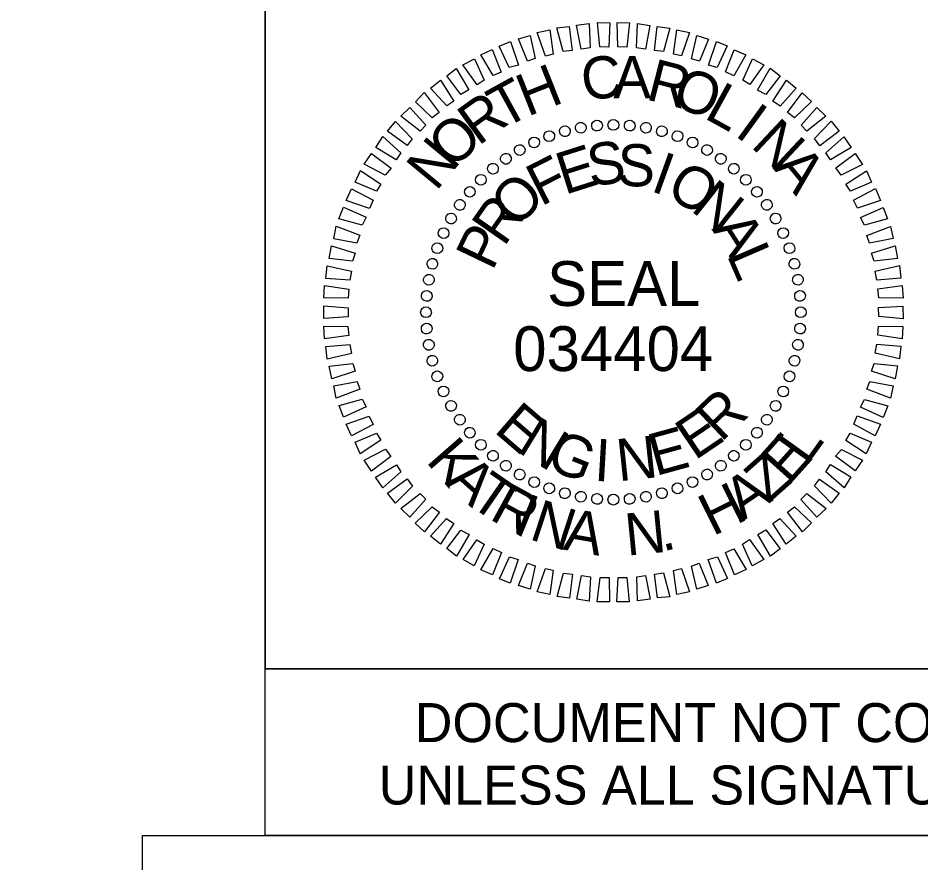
# Model space of a CAD drawing. Extents: x 2320980 to 2456309, y 595047 to 606177.
# Drawn here: x 2455995.13 to 2456020.58, y 596701.59 to 596725.41 of the extents above; entities that cross this region are included whole.
import ezdxf

# ---------------------------------------------------------------- set-up
doc = ezdxf.new("R2010")
doc.units = 0
for name, color, linetype in [('Prop Dimension', 7, 'Continuous'), ('Sheet Data Field CELL', 7, 'Continuous'), ('Sheet Plan CELL', 7, 'Continuous'), ('Sheet Sticker Exception Certification CELL', 7, 'Continuous')]:
    doc.layers.add(name, color=color, linetype=linetype)

msp = doc.modelspace()

# ---------------------------------------------------------------- linework, layer by layer
at = {"layer": 'Prop Dimension'}
msp.add_lwpolyline([(2455998.637, 596702.366), (2456042.107, 596702.366), (2456042.107, 596698.09), (2455998.637, 596698.09)], close=True, dxfattribs=at)
at = {"layer": 'Sheet Data Field CELL'}
for p, q in [((2456010.539, 596722.224), (2456010.539, 596722.224)), ((2456011.001, 596722.316), (2456011.001, 596722.316)), ((2456011.453, 596722.387), (2456011.453, 596722.387)), ((2456011.916, 596722.406), (2456011.916, 596722.406)), ((2456012.38, 596722.383), (2456012.38, 596722.383)), ((2456012.834, 596722.317), (2456012.834, 596722.317)), ((2456013.278, 596722.23), (2456013.278, 596722.23)), ((2456010.099, 596722.09), (2456010.099, 596722.09)), ((2456013.722, 596722.09), (2456013.722, 596722.09)), ((2456009.274, 596721.696), (2456009.274, 596721.696)), ((2456009.681, 596721.914), (2456009.681, 596721.914)), ((2456014.147, 596721.908), (2456014.147, 596721.908)), ((2456014.561, 596721.704), (2456014.561, 596721.704)), ((2456008.878, 596721.447), (2456008.878, 596721.447)), ((2456014.945, 596721.448), (2456014.945, 596721.448)), ((2456008.514, 596721.177), (2456008.514, 596721.177)), ((2456015.319, 596721.17), (2456015.319, 596721.17)), ((2456008.172, 596720.855), (2456008.172, 596720.855)), ((2456015.65, 596720.86), (2456015.65, 596720.86)), ((2456007.862, 596720.523), (2456007.862, 596720.523)), ((2456015.972, 596720.518), (2456015.972, 596720.518)), ((2456007.584, 596720.15), (2456007.584, 596720.15)), ((2456016.242, 596720.154), (2456016.242, 596720.154)), ((2456007.327, 596719.766), (2456007.327, 596719.766)), ((2456016.491, 596719.758), (2456016.491, 596719.758)), ((2456007.124, 596719.352), (2456007.124, 596719.352)), ((2456016.709, 596719.351), (2456016.709, 596719.351)), ((2456006.941, 596718.927), (2456006.941, 596718.927)), ((2456016.885, 596718.932), (2456016.885, 596718.932)), ((2456006.802, 596718.483), (2456006.802, 596718.483)), ((2456017.019, 596718.492), (2456017.019, 596718.492)), ((2456006.715, 596718.039), (2456006.715, 596718.039)), ((2456017.111, 596718.031), (2456017.111, 596718.031)), ((2456006.649, 596717.585), (2456006.649, 596717.585)), ((2456017.183, 596717.579), (2456017.183, 596717.579)), ((2456006.625, 596717.121), (2456006.625, 596717.121)), ((2456017.201, 596717.116), (2456017.201, 596717.116)), ((2456006.644, 596716.658), (2456006.644, 596716.658)), ((2456017.178, 596716.652), (2456017.178, 596716.652)), ((2456006.715, 596716.206), (2456006.715, 596716.206)), ((2456017.112, 596716.198), (2456017.112, 596716.198)), ((2456006.807, 596715.744), (2456006.807, 596715.744)), ((2456017.025, 596715.754), (2456017.025, 596715.754)), ((2456006.942, 596715.304), (2456006.942, 596715.304)), ((2456016.885, 596715.309), (2456016.885, 596715.309)), ((2456007.117, 596714.886), (2456007.117, 596714.886)), ((2456016.703, 596714.884), (2456016.703, 596714.884)), ((2456007.335, 596714.479), (2456007.335, 596714.479)), ((2456016.499, 596714.47), (2456016.499, 596714.47)), ((2456007.584, 596714.083), (2456007.584, 596714.083)), ((2456016.243, 596714.086), (2456016.243, 596714.086)), ((2456007.854, 596713.719), (2456007.854, 596713.719)), ((2456015.965, 596713.713), (2456015.965, 596713.713)), ((2456008.176, 596713.377), (2456008.176, 596713.377)), ((2456015.655, 596713.381), (2456015.655, 596713.381)), ((2456008.508, 596713.067), (2456008.508, 596713.067)), ((2456015.313, 596713.059), (2456015.313, 596713.059)), ((2456008.881, 596712.789), (2456008.881, 596712.789)), ((2456014.949, 596712.789), (2456014.949, 596712.789)), ((2456009.265, 596712.532), (2456009.265, 596712.532)), ((2456014.553, 596712.54), (2456014.553, 596712.54)), ((2456009.679, 596712.329), (2456009.679, 596712.329)), ((2456014.146, 596712.322), (2456014.146, 596712.322)), ((2456010.104, 596712.146), (2456010.104, 596712.146)), ((2456010.549, 596712.007), (2456010.549, 596712.007)), ((2456013.287, 596712.012), (2456013.287, 596712.012)), ((2456013.728, 596712.146), (2456013.728, 596712.146)), ((2456010.993, 596711.92), (2456010.993, 596711.92)), ((2456011.447, 596711.854), (2456011.447, 596711.854)), ((2456011.911, 596711.83), (2456011.911, 596711.83)), ((2456012.374, 596711.849), (2456012.374, 596711.849)), ((2456012.826, 596711.92), (2456012.826, 596711.92))]:
    msp.add_line(p, q, dxfattribs=at)
for points in [[(2456011.004, 596724.539), (2456010.877, 596725.211), (2456011.234, 596725.259), (2456011.256, 596724.575)], [(2456011.53, 596724.601), (2456011.465, 596725.284), (2456011.813, 596725.28), (2456011.783, 596724.595)], [(2456012.035, 596724.599), (2456012.023, 596725.284), (2456012.371, 596725.279), (2456012.288, 596724.593)], [(2456012.563, 596724.577), (2456012.593, 596725.262), (2456012.941, 596725.205), (2456012.816, 596724.539)], [(2456009.996, 596724.342), (2456009.764, 596725.002), (2456010.12, 596725.082), (2456010.217, 596724.399)], [(2456010.5, 596724.467), (2456010.32, 596725.138), (2456010.667, 596725.176), (2456010.752, 596724.503)], [(2456013.07, 596724.501), (2456013.152, 596725.177), (2456013.501, 596725.13), (2456013.323, 596724.474)], [(2456013.609, 596724.395), (2456013.702, 596725.081), (2456014.061, 596725.003), (2456013.831, 596724.346)], [(2456008.98, 596724.019), (2456008.696, 596724.625), (2456009.01, 596724.757), (2456009.243, 596724.087)], [(2456009.493, 596724.197), (2456009.24, 596724.824), (2456009.565, 596724.924), (2456009.713, 596724.274)], [(2456014.116, 596724.267), (2456014.263, 596724.922), (2456014.591, 596724.823), (2456014.339, 596724.197)], [(2456014.593, 596724.085), (2456014.824, 596724.753), (2456015.121, 596724.632), (2456014.837, 596724.016)], [(2456008.521, 596723.79), (2456008.174, 596724.374), (2456008.497, 596724.527), (2456008.751, 596723.889)], [(2456015.071, 596723.894), (2456015.323, 596724.519), (2456015.652, 596724.378), (2456015.305, 596723.782)], [(2456008.073, 596723.529), (2456007.673, 596724.091), (2456007.996, 596724.265), (2456008.27, 596723.659)], [(2456015.559, 596723.66), (2456015.833, 596724.265), (2456016.152, 596724.092), (2456015.762, 596723.537)], [(2456007.614, 596723.258), (2456007.215, 596723.788), (2456007.485, 596723.993), (2456007.843, 596723.388)], [(2456015.975, 596723.383), (2456016.333, 596724), (2456016.611, 596723.784), (2456016.209, 596723.26)], [(2456007.219, 596722.935), (2456006.757, 596723.433), (2456007.038, 596723.659), (2456007.417, 596723.075)], [(2456016.412, 596723.074), (2456016.792, 596723.66), (2456017.07, 596723.433), (2456016.615, 596722.93)], [(2456006.804, 596722.601), (2456006.332, 596723.056), (2456006.581, 596723.314), (2456007.001, 596722.752)], [(2456016.818, 596722.755), (2456017.24, 596723.31), (2456017.498, 596723.062), (2456017.021, 596722.6)], [(2456006.463, 596722.226), (2456005.918, 596722.649), (2456006.177, 596722.896), (2456006.628, 596722.398)], [(2456017.204, 596722.393), (2456017.648, 596722.896), (2456017.905, 596722.647), (2456017.365, 596722.227)], [(2456006.101, 596721.82), (2456005.546, 596722.221), (2456005.773, 596722.499), (2456006.245, 596722.012)], [(2456017.579, 596722.02), (2456018.055, 596722.503), (2456018.281, 596722.222), (2456017.73, 596721.812)], [(2456005.792, 596721.414), (2456005.217, 596721.762), (2456005.412, 596722.071), (2456005.926, 596721.617)], [(2456017.902, 596721.615), (2456018.41, 596722.066), (2456018.616, 596721.764), (2456018.032, 596721.417)], [(2456005.484, 596720.988), (2456004.888, 596721.293), (2456005.094, 596721.592), (2456005.649, 596721.18)], [(2456018.183, 596721.188), (2456018.734, 596721.598), (2456018.94, 596721.286), (2456018.334, 596720.98)], [(2456005.239, 596720.53), (2456004.634, 596720.783), (2456004.786, 596721.112), (2456005.362, 596720.733)], [(2456018.465, 596720.73), (2456019.048, 596721.108), (2456019.191, 596720.784), (2456018.595, 596720.532)], [(2456005.037, 596720.042), (2456004.379, 596720.273), (2456004.532, 596720.602), (2456005.138, 596720.276)], [(2456018.684, 596720.281), (2456019.299, 596720.607), (2456019.442, 596720.273), (2456018.793, 596720.051)], [(2456004.834, 596719.575), (2456004.178, 596719.753), (2456004.309, 596720.082), (2456004.946, 596719.798)], [(2456018.882, 596719.789), (2456019.519, 596720.074), (2456019.641, 596719.749), (2456018.991, 596719.57)], [(2456004.685, 596719.067), (2456004.03, 596719.193), (2456004.097, 596719.541), (2456004.765, 596719.29)], [(2456019.059, 596719.286), (2456019.729, 596719.54), (2456019.798, 596719.194), (2456019.137, 596719.067)], [(2456004.557, 596718.559), (2456003.902, 596718.632), (2456003.97, 596718.991), (2456004.637, 596718.782)], [(2456019.194, 596718.783), (2456019.854, 596718.995), (2456019.924, 596718.638), (2456019.261, 596718.563)], [(2456004.482, 596718.021), (2456003.807, 596718.072), (2456003.843, 596718.431), (2456004.53, 596718.274)], [(2456019.298, 596718.279), (2456019.98, 596718.439), (2456020.018, 596718.081), (2456019.345, 596718.027)], [(2456004.438, 596717.514), (2456003.753, 596717.523), (2456003.768, 596717.871), (2456004.455, 596717.767)], [(2456019.37, 596717.775), (2456020.053, 596717.871), (2456020.08, 596717.514), (2456019.395, 596717.523)], [(2456004.437, 596716.988), (2456003.753, 596716.944), (2456003.747, 596717.302), (2456004.432, 596717.24)], [(2456019.39, 596717.249), (2456020.074, 596717.292), (2456020.08, 596716.934), (2456019.394, 596716.996)], [(2456004.456, 596716.461), (2456003.774, 596716.365), (2456003.746, 596716.723), (2456004.431, 596716.714)], [(2456019.388, 596716.722), (2456020.073, 596716.713), (2456020.058, 596716.365), (2456019.372, 596716.469)], [(2456004.529, 596715.957), (2456003.847, 596715.798), (2456003.809, 596716.155), (2456004.482, 596716.209)], [(2456019.344, 596716.216), (2456020.02, 596716.164), (2456019.984, 596715.805), (2456019.296, 596715.962)], [(2456004.632, 596715.453), (2456003.972, 596715.242), (2456003.903, 596715.598), (2456004.565, 596715.673)], [(2456019.27, 596715.677), (2456019.924, 596715.604), (2456019.856, 596715.245), (2456019.189, 596715.454)], [(2456004.767, 596714.95), (2456004.098, 596714.696), (2456004.028, 596715.042), (2456004.69, 596715.17)], [(2456019.142, 596715.169), (2456019.797, 596715.044), (2456019.729, 596714.695), (2456019.061, 596714.947)], [(2456004.945, 596714.447), (2456004.307, 596714.162), (2456004.186, 596714.487), (2456004.835, 596714.667)], [(2456018.992, 596714.661), (2456019.649, 596714.483), (2456019.517, 596714.154), (2456018.88, 596714.438)], [(2456005.143, 596713.956), (2456004.527, 596713.629), (2456004.384, 596713.964), (2456005.033, 596714.186)], [(2456018.79, 596714.194), (2456019.447, 596713.963), (2456019.295, 596713.634), (2456018.689, 596713.961)], [(2456005.361, 596713.507), (2456004.778, 596713.128), (2456004.635, 596713.452), (2456005.231, 596713.705)], [(2456018.588, 596713.706), (2456019.193, 596713.453), (2456019.04, 596713.124), (2456018.465, 596713.504)], [(2456005.643, 596713.048), (2456005.092, 596712.638), (2456004.886, 596712.951), (2456005.492, 596713.256)], [(2456018.343, 596713.249), (2456018.938, 596712.943), (2456018.733, 596712.645), (2456018.178, 596713.056)], [(2456005.924, 596712.621), (2456005.416, 596712.17), (2456005.211, 596712.472), (2456005.795, 596712.819)], [(2456018.034, 596712.822), (2456018.609, 596712.474), (2456018.415, 596712.165), (2456017.901, 596712.62)], [(2456006.248, 596712.216), (2456005.771, 596711.734), (2456005.545, 596712.014), (2456006.096, 596712.424)], [(2456017.725, 596712.416), (2456018.28, 596712.015), (2456018.053, 596711.737), (2456017.581, 596712.224)], [(2456006.623, 596711.843), (2456006.179, 596711.341), (2456005.921, 596711.589), (2456006.462, 596712.009)], [(2456017.364, 596712.01), (2456017.909, 596711.587), (2456017.649, 596711.341), (2456017.198, 596711.838)], [(2456007.008, 596711.481), (2456006.586, 596710.926), (2456006.329, 596711.175), (2456006.805, 596711.636)], [(2456017.023, 596711.635), (2456017.494, 596711.18), (2456017.246, 596710.923), (2456016.825, 596711.484)], [(2456007.414, 596711.162), (2456007.035, 596710.576), (2456006.757, 596710.803), (2456007.212, 596711.306)], [(2456016.607, 596711.301), (2456017.069, 596710.804), (2456016.788, 596710.578), (2456016.41, 596711.161)], [(2456007.851, 596710.854), (2456007.493, 596710.236), (2456007.216, 596710.453), (2456007.617, 596710.976)], [(2456016.213, 596710.979), (2456016.612, 596710.448), (2456016.341, 596710.243), (2456015.983, 596710.848)], [(2456008.267, 596710.577), (2456007.993, 596709.971), (2456007.674, 596710.145), (2456008.065, 596710.699)], [(2456015.754, 596710.707), (2456016.154, 596710.145), (2456015.83, 596709.971), (2456015.556, 596710.577)], [(2456008.756, 596710.343), (2456008.503, 596709.717), (2456008.174, 596709.859), (2456008.522, 596710.455)], [(2456009.233, 596710.151), (2456009.002, 596709.483), (2456008.705, 596709.604), (2456008.989, 596710.22)], [(2456014.846, 596710.217), (2456015.131, 596709.611), (2456014.817, 596709.479), (2456014.584, 596710.149)], [(2456015.306, 596710.446), (2456015.653, 596709.863), (2456015.329, 596709.71), (2456015.076, 596710.348)], [(2456009.71, 596709.97), (2456009.564, 596709.314), (2456009.235, 596709.414), (2456009.488, 596710.039)], [(2456014.333, 596710.04), (2456014.586, 596709.412), (2456014.262, 596709.312), (2456014.113, 596709.962)], [(2456010.218, 596709.842), (2456010.125, 596709.155), (2456009.765, 596709.233), (2456009.996, 596709.89)], [(2456010.757, 596709.735), (2456010.674, 596709.06), (2456010.326, 596709.106), (2456010.504, 596709.762)], [(2456013.327, 596709.769), (2456013.507, 596709.098), (2456013.16, 596709.061), (2456013.074, 596709.733)], [(2456013.83, 596709.894), (2456014.063, 596709.235), (2456013.706, 596709.155), (2456013.61, 596709.838)], [(2456011.264, 596709.66), (2456011.234, 596708.975), (2456010.885, 596709.032), (2456011.01, 596709.697)], [(2456011.791, 596709.637), (2456011.803, 596708.953), (2456011.455, 596708.957), (2456011.538, 596709.643)], [(2456012.297, 596709.636), (2456012.361, 596708.952), (2456012.014, 596708.957), (2456012.044, 596709.642)], [(2456012.822, 596709.697), (2456012.95, 596709.026), (2456012.593, 596708.977), (2456012.57, 596709.661)]]:
    msp.add_lwpolyline(points, close=True, dxfattribs=at)
for centre, major_axis in [((2456010.996, 596722.321), (-0.026, 0.149)), ((2456011.453, 596722.381), (-0.013, 0.151)), ((2456011.913, 596722.401), (0, 0.152)), ((2456012.374, 596722.381), (0.013, 0.151)), ((2456012.831, 596722.321), (0.026, 0.149)), ((2456010.106, 596722.082), (-0.052, 0.143)), ((2456010.546, 596722.221), (-0.039, 0.146)), ((2456013.281, 596722.221), (0.039, 0.146)), ((2456013.72, 596722.082), (0.052, 0.143)), ((2456009.681, 596721.906), (-0.064, 0.137)), ((2456014.146, 596721.906), (0.064, 0.137)), ((2456009.272, 596721.693), (-0.076, 0.131)), ((2456014.555, 596721.693), (0.076, 0.131)), ((2456008.883, 596721.446), (-0.087, 0.124)), ((2456014.943, 596721.446), (0.087, 0.124)), ((2456008.518, 596721.165), (-0.097, 0.116)), ((2456015.309, 596721.165), (0.097, 0.116)), ((2456008.178, 596720.854), (-0.107, 0.107)), ((2456015.649, 596720.854), (0.107, 0.107)), ((2456007.866, 596720.514), (-0.116, 0.097)), ((2456015.96, 596720.514), (0.116, 0.097)), ((2456007.586, 596720.148), (-0.124, 0.087)), ((2456016.241, 596720.148), (0.124, 0.087)), ((2456007.338, 596719.76), (-0.131, 0.076)), ((2456016.488, 596719.76), (0.131, 0.076)), ((2456007.125, 596719.351), (-0.137, 0.064)), ((2456016.701, 596719.351), (0.137, 0.064)), ((2456006.949, 596718.925), (-0.143, 0.052)), ((2456016.877, 596718.925), (0.143, 0.052)), ((2456006.81, 596718.485), (-0.146, 0.039)), ((2456017.016, 596718.485), (0.146, 0.039)), ((2456006.711, 596718.035), (-0.149, 0.026)), ((2456017.116, 596718.035), (0.149, 0.026)), ((2456006.651, 596717.579), (-0.151, 0.013)), ((2456017.176, 596717.579), (0.151, 0.013)), ((2456006.63, 596717.118), (-0.152, 0)), ((2456017.196, 596717.118), (0.152, 0)), ((2456006.651, 596716.658), (-0.151, -0.013)), ((2456017.176, 596716.658), (0.151, -0.013)), ((2456006.711, 596716.201), (-0.149, -0.026)), ((2456017.116, 596716.201), (0.149, -0.026)), ((2456006.81, 596715.751), (-0.146, -0.039)), ((2456017.016, 596715.751), (0.146, -0.039)), ((2456006.949, 596715.311), (-0.143, -0.052)), ((2456016.877, 596715.311), (0.143, -0.052)), ((2456007.125, 596714.886), (-0.137, -0.064)), ((2456016.701, 596714.886), (0.137, -0.064)), ((2456007.338, 596714.477), (-0.131, -0.076)), ((2456016.488, 596714.477), (0.131, -0.076)), ((2456007.586, 596714.088), (-0.124, -0.087)), ((2456016.241, 596714.088), (0.124, -0.087)), ((2456007.866, 596713.722), (-0.116, -0.097)), ((2456015.96, 596713.722), (0.116, -0.097)), ((2456008.178, 596713.383), (-0.107, -0.107)), ((2456015.649, 596713.383), (0.107, -0.107)), ((2456008.518, 596713.071), (-0.097, -0.116)), ((2456015.309, 596713.071), (0.097, -0.116)), ((2456008.883, 596712.791), (-0.087, -0.124)), ((2456014.943, 596712.791), (0.087, -0.124)), ((2456009.272, 596712.543), (-0.076, -0.131)), ((2456009.681, 596712.33), (-0.064, -0.137)), ((2456014.146, 596712.33), (0.064, -0.137)), ((2456014.555, 596712.543), (0.076, -0.131)), ((2456010.106, 596712.154), (-0.052, -0.143)), ((2456013.72, 596712.154), (0.052, -0.143)), ((2456010.546, 596712.015), (-0.039, -0.146)), ((2456010.996, 596711.916), (-0.026, -0.149)), ((2456011.453, 596711.855), (-0.013, -0.151)), ((2456012.374, 596711.855), (0.013, -0.151)), ((2456012.831, 596711.916), (0.026, -0.149)), ((2456013.281, 596712.015), (0.039, -0.146)), ((2456011.913, 596711.835), (0, -0.152))]:
    msp.add_ellipse(centre, major_axis=major_axis, ratio=0.999708, dxfattribs=at)
at = {"layer": 'Sheet Plan CELL'}
for points in [[(2455742.104, 596527.076), (2455742.099, 596737.071), (2456002.097, 596737.079), (2456002.099, 596707.066), (2456042.107, 596707.064), (2456042.107, 596527.076)], [(2456002.097, 596729.564), (2456022.107, 596729.564), (2456022.107, 596707.061), (2456002.099, 596707.066)]]:
    msp.add_lwpolyline(points, close=True, dxfattribs=at)
at = {"layer": 'Sheet Sticker Exception Certification CELL'}
for p, q in [((2456002.099, 596702.366), (2456002.099, 596707.066)), ((2456002.099, 596707.066), (2456042.107, 596707.066)), ((2456042.107, 596702.366), (2456002.099, 596702.366))]:
    msp.add_line(p, q, dxfattribs=at)

# ---------------------------------------------------------------- texts
at = {"layer": 'Sheet Data Field CELL'}
for s, height, rotation, p in [('C', 1.188, 7.2199, (2456011.082, 596723.076)), ('A', 1.187, 0.0203, (2456011.913, 596723.154)), ('R', 1.188, 345.6211, (2456012.798, 596723.127)), ('H', 1.188, 21.6195, (2456009.489, 596722.627)), ('O', 1.187, 338.4212, (2456013.507, 596722.981)), ('T', 1.188, 28.8198, (2456008.811, 596722.267)), ('L', 1.188, 331.2209, (2456014.44, 596722.608)), ('R', 1.188, 36.0205, (2456008.103, 596721.792)), ('I', 1.188, 324.0201, (2456015.302, 596722.117)), ('O', 1.188, 43.2217, (2456007.388, 596721.126)), ('N', 1.188, 316.8189, (2456015.761, 596721.799)), ('N', 1.188, 50.4235, (2456006.914, 596720.507)), ('S', 1.188, 8.2556, (2456011.262, 596720.657)), ('E', 1.188, 17.6111, (2456010.539, 596720.423)), ('S', 1.188, 358.9004, (2456012.02, 596720.68)), ('F', 1.187, 26.967, (2456009.871, 596720.095)), ('I', 1.188, 340.1896, (2456012.928, 596720.549)), ('A', 1.188, 309.6172, (2456016.393, 596721.188)), ('O', 1.187, 330.8335, (2456013.352, 596720.409)), ('O', 1.188, 45.6812, (2456009.186, 596719.462)), ('N', 1.188, 321.4766, (2456014.064, 596720)), ('R', 1.188, 55.0397, (2456008.827, 596718.939)), ('A', 1.188, 302.7603, (2456014.674, 596719.463)), ('P', 1.188, 64.3989, (2456008.502, 596718.259)), ('L', 1.188, 293.4009, (2456015.098, 596718.743)), ('SEAL', 1.2634, 0, (2456010.046, 596717.296)), ('034404', 1.2638, 0, (2456009.089, 596715.46)), ('R', 1.188, 43.4814, (2456014.948, 596713.432)), ('E', 1.188, 319.2769, (2456008.517, 596713.762)), ('E', 1.188, 34.1241, (2456014.209, 596712.924)), ('N', 1.188, 328.634, (2456009.159, 596713.204)), ('E', 1.188, 15.4118, (2456013.1, 596712.494)), ('K', 1.188, 311.168, (2456006.605, 596712.914)), ('G', 1.188, 337.9902, (2456009.967, 596712.744)), ('I', 1.188, 356.7012, (2456011.354, 596712.368)), ('N', 1.188, 6.0564, (2456012.06, 596712.349)), ('E', 1.188, 48.1243, (2456016.869, 596712.232)), ('L', 1.188, 54.2991, (2456017.366, 596712.78)), ('Z', 1.188, 41.5848, (2456016.281, 596711.714)), ('A', 1.188, 318.0722, (2456007.149, 596712.292)), ('T', 1.188, 325.3219, (2456007.797, 596711.713)), ('A', 1.188, 34.3351, (2456015.565, 596711.222)), ('R', 1.188, 331.3047, (2456008.384, 596711.301)), ('H', 1.188, 26.3751, (2456014.715, 596710.79)), ('I', 1.188, 337.7098, (2456009.055, 596710.929)), ('N', 1.188, 341.8307, (2456009.508, 596710.731)), ('A', 1.188, 350.2514, (2456010.47, 596710.429)), ('N', 1.188, 5.5954, (2456012.296, 596710.252)), ('.', 1.188, 14.016, (2456013.299, 596710.364))]:
    msp.add_text(s, height=height, rotation=rotation, dxfattribs=at).set_placement(p)
at = {"layer": 'Sheet Sticker Exception Certification CELL'}
for s, p in [('DOCUMENT NOT CONSIDERED FINAL', (2456006.313, 596704.997)), ('UNLESS ALL SIGNATURES COMPLETED', (2456005.299, 596703.237))]:
    msp.add_text(s, height=1.1, dxfattribs=at).set_placement(p)

doc.saveas('drawing.dxf')
